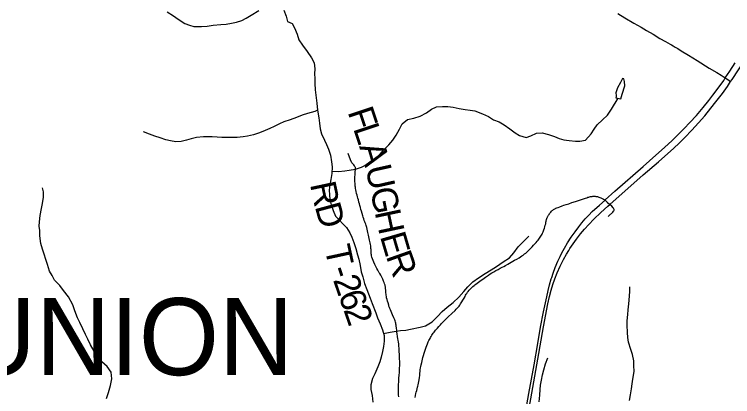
# Model space of a CAD drawing. Extents: x 0 to 34, y 0 to 22.
# Drawn here: x 5.781 to 7.37, y 19.464 to 20.31 of the extents above; entities that cross this region are included whole.
import ezdxf

# ---------------------------------------------------------------- set-up
doc = ezdxf.new("R2010")
doc.units = 0
for name, color, linetype in [('GM_X_County_Road', 7, 'Continuous'), ('GM_X_Minor_Lake', 7, 'Continuous'), ('GM_X_Minor_River', 7, 'Continuous'), ('GM_X_Township_Road', 7, 'Continuous'), ('GM_X_Township_Road_Text', 7, 'Continuous'), ('GM_X_Township_Text', 7, 'Continuous'), ('GM_X_US_Route', 7, 'Continuous')]:
    doc.layers.add(name, color=color, linetype=linetype)

msp = doc.modelspace()

# ---------------------------------------------------------------- linework, layer by layer
at = {"layer": 'GM_X_County_Road'}
for points in [[(6.9602, 19.8606), (6.9605, 19.8614), (6.9611, 19.8628), (6.9618, 19.8639), (6.9626, 19.8652), (6.9638, 19.8671), (6.9651, 19.8689), (6.9663, 19.8706), (6.9678, 19.8723), (6.9693, 19.8739), (6.9708, 19.8753), (6.9723, 19.8764), (6.9739, 19.8776), (6.9751, 19.8784), (6.9763, 19.8791), (6.9778, 19.88), (6.9791, 19.8806), (6.9809, 19.8814), (6.9837, 19.8824), (6.9874, 19.8838), (6.9927, 19.8857), (6.9968, 19.8872), (7.0018, 19.8888), (7.0076, 19.8907), (7.0145, 19.893), (7.0226, 19.8958), (7.0447, 19.9032), (7.0474, 19.904), (7.0499, 19.9048), (7.0518, 19.9054), (7.0535, 19.9058), (7.0553, 19.9063), (7.0572, 19.9067), (7.059, 19.9069), (7.0607, 19.9071), (7.0625, 19.9072), (7.0641, 19.9072), (7.0659, 19.9071), (7.0675, 19.9069), (7.0692, 19.9068), (7.071, 19.9064), (7.0724, 19.906), (7.0741, 19.9054), (7.0765, 19.9046), (7.0788, 19.9036), (7.0812, 19.9025), (7.0842, 19.9009), (7.0877, 19.8986)], [(7.0877, 19.8986), (7.0928, 19.894), (7.0982, 19.8889)], [(6.6674, 19.4617), (6.6683, 19.4666), (6.6694, 19.4706), (6.67, 19.474), (6.671, 19.4776), (6.672, 19.4811), (6.6731, 19.4849), (6.6738, 19.4873), (6.6744, 19.4902), (6.6751, 19.4934), (6.6757, 19.497), (6.6764, 19.5008), (6.6773, 19.5065), (6.6777, 19.5104), (6.678, 19.5134), (6.6782, 19.516), (6.6786, 19.5196), (6.679, 19.5234), (6.6797, 19.5272), (6.6803, 19.5307), (6.6811, 19.5342), (6.6821, 19.5393), (6.6829, 19.5428), (6.6837, 19.5464), (6.6848, 19.5507), (6.6859, 19.555), (6.6874, 19.5602), (6.6887, 19.5642), (6.6905, 19.5692), (6.6919, 19.5733), (6.6933, 19.5772), (6.6947, 19.5807), (6.6956, 19.583), (6.6967, 19.5853), (6.6979, 19.5877), (6.6991, 19.59), (6.7005, 19.5927), (6.7015, 19.5946), (6.703, 19.597), (6.7048, 19.5998), (6.7062, 19.6019), (6.7078, 19.6043), (6.7095, 19.6066), (6.7112, 19.6088), (6.7128, 19.6108), (6.7144, 19.6127), (6.7167, 19.6154), (6.7197, 19.6188), (6.7234, 19.623), (6.726, 19.6256), (6.7288, 19.6286), (6.7311, 19.631), (6.7339, 19.6338), (6.7371, 19.6369), (6.7408, 19.6405), (6.7487, 19.6479), (6.7558, 19.6546), (6.7587, 19.6575), (6.7606, 19.6597), (6.7626, 19.6619), (6.7648, 19.6643), (6.7662, 19.6664), (6.768, 19.6689), (6.7694, 19.6711), (6.771, 19.6738), (6.7729, 19.6771), (6.7758, 19.682), (6.778, 19.6857), (6.7793, 19.6881), (6.7806, 19.6902), (6.7819, 19.6922), (6.7837, 19.6946), (6.7852, 19.6967), (6.7871, 19.6991), (6.7886, 19.7008), (6.7902, 19.7026), (6.7916, 19.704), (6.7931, 19.7054), (6.7954, 19.7075), (6.7978, 19.7095), (6.7997, 19.711), (6.8018, 19.7126), (6.805, 19.7151), (6.8138, 19.7215), (6.8174, 19.724), (6.8234, 19.7283), (6.8297, 19.7326), (6.8338, 19.7353), (6.8373, 19.7375), (6.8417, 19.7401), (6.8463, 19.7428), (6.8512, 19.7454), (6.8559, 19.7479), (6.8599, 19.7501), (6.8635, 19.752), (6.8677, 19.7542), (6.8724, 19.7568), (6.8877, 19.7654), (6.8928, 19.7683), (6.8976, 19.7711), (6.9005, 19.7729), (6.9038, 19.7751), (6.9067, 19.777), (6.9099, 19.7794), (6.9124, 19.7815), (6.9148, 19.7836), (6.9174, 19.7861), (6.9201, 19.7889), (6.9236, 19.7926), (6.9264, 19.7955), (6.9296, 19.7987), (6.9324, 19.8019), (6.9351, 19.805), (6.9373, 19.8075), (6.9395, 19.8102), (6.9413, 19.8124), (6.943, 19.8146), (6.9444, 19.8167), (6.9458, 19.8187), (6.9472, 19.8213), (6.9483, 19.8233), (6.9495, 19.8257), (6.9506, 19.8281), (6.9516, 19.8305), (6.9526, 19.8332), (6.9537, 19.8362), (6.9546, 19.8396), (6.9556, 19.8433), (6.9564, 19.8464), (6.9571, 19.8496), (6.9578, 19.8524), (6.9585, 19.8555), (6.9593, 19.8582), (6.9599, 19.8599), (6.9602, 19.8606)]]:
    msp.add_lwpolyline(points, dxfattribs=at)
at = {"layer": 'GM_X_Minor_Lake'}
for points in [[(7.1228, 20.1227), (7.1259, 20.1329), (7.1315, 20.1514), (7.1305, 20.1613), (7.129, 20.1666), (7.1264, 20.1678), (7.1217, 20.1591), (7.1151, 20.1467), (7.1119, 20.1357), (7.1122, 20.13)], [(7.1122, 20.13), (7.1121, 20.1272), (7.1114, 20.1249), (7.1228, 20.1227)]]:
    msp.add_lwpolyline(points, dxfattribs=at)
at = {"layer": 'GM_X_Minor_River'}
for points in [[(6.119, 20.3149), (6.1329, 20.3064), (6.1431, 20.2986), (6.1581, 20.2897), (6.1683, 20.2858), (6.1781, 20.2826), (6.1948, 20.2824), (6.2073, 20.2837), (6.2206, 20.2855), (6.2377, 20.2871), (6.2495, 20.2881), (6.2616, 20.2898), (6.2723, 20.2923), (6.2841, 20.296), (6.294, 20.3011), (6.3051, 20.3078), (6.3219, 20.3182)], [(6.3772, 20.319), (6.3824, 20.3053), (6.3849, 20.2939), (6.3954, 20.2895), (6.4003, 20.28), (6.4065, 20.2659), (6.4101, 20.2529), (6.4183, 20.2411), (6.4284, 20.2277), (6.4385, 20.2135), (6.4444, 20.202), (6.4457, 20.1888), (6.4452, 20.1781), (6.4455, 20.1675), (6.4453, 20.1569), (6.4463, 20.1425), (6.4483, 20.1246), (6.4497, 20.1132), (6.4518, 20.0973), (6.4542, 20.0809), (6.4556, 20.0688), (6.4577, 20.0566), (6.4606, 20.0452), (6.4669, 20.0311), (6.4713, 20.0216), (6.4757, 20.0113), (6.4801, 19.9979), (6.4826, 19.9835), (6.4839, 19.9725), (6.483, 19.9573), (6.4809, 19.9441), (6.4789, 19.9327), (6.4776, 19.9206), (6.4779, 19.9104), (6.4785, 19.9001), (6.4814, 19.8879), (6.4865, 19.8754), (6.4917, 19.8628), (6.516, 19.8378), (6.5234, 19.8263), (6.5275, 19.8164), (6.5319, 19.8046), (6.5366, 19.7913), (6.5402, 19.7776), (6.5432, 19.7677), (6.546, 19.754), (6.5485, 19.7399), (6.5518, 19.7289), (6.5554, 19.714), (6.5605, 19.7011), (6.5642, 19.6911), (6.5679, 19.6816), (6.5723, 19.6698), (6.5803, 19.6492), (6.584, 19.6385), (6.5899, 19.6248), (6.5954, 19.6118), (6.5987, 19.5993), (6.5993, 19.5864), (6.5976, 19.5746), (6.5952, 19.5637), (6.5924, 19.5512), (6.5892, 19.5406), (6.5853, 19.5297), (6.5786, 19.5146), (6.5732, 19.5037), (6.5696, 19.4897), (6.5695, 19.4795), (6.5727, 19.4662), (6.5737, 19.4517)], [(6.4833, 19.9628), (6.4978, 19.9617), (6.5119, 19.9637), (6.5218, 19.9648), (6.5358, 19.9668), (6.5491, 19.9712), (6.564, 19.9793), (6.5759, 19.9871), (6.587, 19.9965), (6.5974, 20.0089), (6.6093, 20.0212), (6.6181, 20.0309), (6.6255, 20.0426), (6.6332, 20.0554), (6.6387, 20.0671), (6.6509, 20.0768), (6.665, 20.0796), (6.6787, 20.0843), (6.6928, 20.0914), (6.7039, 20.0995), (6.7146, 20.1051), (6.7279, 20.106), (6.7396, 20.1059), (6.7514, 20.1042), (6.765, 20.1014), (6.7782, 20.0993), (6.7892, 20.0976), (6.7994, 20.096), (6.8164, 20.0893), (6.8296, 20.0838), (6.8409, 20.0765), (6.8537, 20.0717), (6.8642, 20.0655), (6.8774, 20.0566), (6.889, 20.0477), (6.8988, 20.0415), (6.9132, 20.0372), (6.9235, 20.0408), (6.9364, 20.0467), (6.9489, 20.0473), (6.9629, 20.0437), (6.9758, 20.039), (6.9859, 20.035), (6.9965, 20.0322), (7.0086, 20.0302), (7.0223, 20.0289), (7.0321, 20.0291), (7.0443, 20.0316), (7.057, 20.0455), (7.0639, 20.0556), (7.0701, 20.0654), (7.082, 20.0762), (7.0931, 20.0867), (7.102, 20.0998), (7.1168, 20.1238)], [(6.4518, 20.0974), (6.4457, 20.0947), (6.4293, 20.09), (6.4175, 20.0864), (6.405, 20.0816), (6.3909, 20.0765), (6.3771, 20.0718), (6.3672, 20.0673), (6.3558, 20.0618), (6.3463, 20.057), (6.336, 20.0526), (6.3234, 20.0475), (6.3101, 20.0427), (6.2964, 20.0399), (6.2869, 20.0389), (6.274, 20.0375), (6.2645, 20.0373), (6.2535, 20.037), (6.2402, 20.0372), (6.2296, 20.0381), (6.2186, 20.0386), (6.2088, 20.0388), (6.1993, 20.0385), (6.1837, 20.0372), (6.1719, 20.0343), (6.1613, 20.0311), (6.1499, 20.0282), (6.1377, 20.0276), (6.1264, 20.0296), (6.1162, 20.0321), (6.1034, 20.0364), (6.0916, 20.0403), (6.0796, 20.0443), (6.0664, 20.0498)], [(5.985, 19.4597), (5.9893, 19.4729), (5.9933, 19.4884), (5.9962, 19.5031), (5.9948, 19.518), (5.9859, 19.5302), (5.9746, 19.5406), (5.9642, 19.5536), (5.9571, 19.5643), (5.9493, 19.5785), (5.943, 19.5911), (5.9379, 19.601), (5.9323, 19.614), (5.9253, 19.6277), (5.9205, 19.6384), (5.9146, 19.654), (5.9103, 19.667), (5.9006, 19.6849), (5.8894, 19.6987), (5.8812, 19.7099), (5.8696, 19.7218), (5.8641, 19.7317), (5.8585, 19.7413), (5.8538, 19.7561), (5.8505, 19.7675), (5.8465, 19.7793), (5.8432, 19.79), (5.8392, 19.8026), (5.8371, 19.8197), (5.8369, 19.8314), (5.8359, 19.8413), (5.8364, 19.8508), (5.8377, 19.8648), (5.8405, 19.8803), (5.8433, 19.8912), (5.8454, 19.9052), (5.8455, 19.9166), (5.8434, 19.9261)], [(6.5975, 19.6036), (6.612, 19.6063), (6.6253, 19.6084), (6.6352, 19.6098), (6.647, 19.6111), (6.6576, 19.6129), (6.6789, 19.6172), (6.6903, 19.6208), (6.7052, 19.6293), (6.7171, 19.6413), (6.7271, 19.6525), (6.7386, 19.6615), (6.752, 19.6723), (6.7646, 19.6839), (6.775, 19.6966), (6.7839, 19.7067), (6.795, 19.718), (6.808, 19.7265), (6.8226, 19.7365), (6.8355, 19.7447), (6.8478, 19.7521), (6.8627, 19.7618), (6.8761, 19.7707), (6.8861, 19.7819), (6.8957, 19.7955), (6.908, 19.8078), (6.9188, 19.819)], [(7.142, 19.455), (7.1444, 19.4675), (7.1465, 19.4811), (7.1474, 19.4924), (7.1494, 19.5023), (7.1519, 19.5197), (7.1517, 19.5326), (7.1511, 19.5428), (7.1482, 19.5573), (7.1446, 19.5683), (7.1399, 19.5843), (7.1381, 19.5946), (7.1371, 19.6056), (7.1365, 19.6223), (7.137, 19.6318), (7.138, 19.6454), (7.1392, 19.6556), (7.1405, 19.6693), (7.1419, 19.6859), (7.1424, 19.6969), (7.1429, 19.7064)], [(6.9422, 19.4524), (6.9435, 19.4668), (6.9444, 19.4793), (6.9453, 19.4891), (6.947, 19.5005), (6.9494, 19.5122), (6.9522, 19.5232), (6.9558, 19.5364), (6.9609, 19.55)]]:
    msp.add_lwpolyline(points, dxfattribs=at)
at = {"layer": 'GM_X_Township_Road'}
for points in [[(7.1163, 20.3115), (7.1318, 20.3021), (7.1518, 20.2903), (7.168, 20.2809), (7.1794, 20.2742), (7.1939, 20.2656), (7.2093, 20.2564), (7.2218, 20.2492), (7.2269, 20.2462), (7.2315, 20.2438), (7.2345, 20.2421), (7.2382, 20.2399), (7.2431, 20.2371), (7.2487, 20.2338), (7.2565, 20.2289), (7.2723, 20.219), (7.2913, 20.2073), (7.3185, 20.1907), (7.3348, 20.1807), (7.3446, 20.1747), (7.3539, 20.1688)], [(7.3539, 20.1688), (7.3594, 20.1651), (7.3657, 20.1608)], [(6.6312, 19.4632), (6.6311, 19.468), (6.631, 19.4746), (6.631, 19.4804), (6.631, 19.4859), (6.6311, 19.491), (6.6313, 19.4966), (6.6314, 19.5005), (6.6316, 19.5045), (6.6321, 19.5115), (6.6326, 19.517), (6.6331, 19.5264), (6.6335, 19.5333), (6.6335, 19.5378), (6.6334, 19.5423), (6.6333, 19.5467), (6.6332, 19.5508), (6.633, 19.5565), (6.6325, 19.5643), (6.6322, 19.5705), (6.6317, 19.576), (6.6313, 19.5804), (6.6307, 19.5844), (6.6302, 19.5885), (6.6296, 19.5918), (6.6287, 19.597), (6.6278, 19.6029), (6.6273, 19.6064), (6.6268, 19.6098), (6.6261, 19.616), (6.6257, 19.62), (6.6255, 19.6222), (6.6252, 19.6243), (6.6248, 19.6264), (6.6243, 19.6288), (6.6233, 19.6315), (6.6224, 19.634), (6.6205, 19.6385), (6.6178, 19.6446), (6.6143, 19.6523), (6.6128, 19.6556), (6.6115, 19.6589), (6.6106, 19.6612), (6.6097, 19.6638), (6.609, 19.6663), (6.6076, 19.671), (6.6065, 19.675), (6.6054, 19.679), (6.6045, 19.6827), (6.6039, 19.6856), (6.6034, 19.6884), (6.6031, 19.6909), (6.6029, 19.6933), (6.6027, 19.6962), (6.6025, 19.6995), (6.6022, 19.7031), (6.6018, 19.7064), (6.6015, 19.7083), (6.6009, 19.7108), (6.6001, 19.7134), (6.5991, 19.7161), (6.5978, 19.7195), (6.5963, 19.7234), (6.5949, 19.7266), (6.5934, 19.7295), (6.5917, 19.7327), (6.5897, 19.7359), (6.5883, 19.738), (6.5868, 19.7406), (6.5851, 19.7433), (6.5831, 19.747), (6.5815, 19.75), (6.5799, 19.7531), (6.5785, 19.7562), (6.5764, 19.761), (6.5746, 19.7651), (6.5731, 19.769), (6.5719, 19.7726), (6.5712, 19.7751), (6.5707, 19.7774), (6.5702, 19.7799), (6.57, 19.7836), (6.5699, 19.7867), (6.5699, 19.789), (6.5698, 19.7917), (6.5697, 19.7946), (6.5694, 19.7973), (6.569, 19.8002), (6.5681, 19.8044), (6.5676, 19.8068), (6.5668, 19.8098), (6.566, 19.8135), (6.5651, 19.8174), (6.5641, 19.8212), (6.5634, 19.8242), (6.5628, 19.8269), (6.562, 19.8307), (6.5612, 19.8344), (6.5605, 19.8378), (6.5599, 19.8399), (6.5591, 19.8424), (6.5581, 19.8456), (6.557, 19.8486), (6.5561, 19.8509), (6.5551, 19.8537), (6.554, 19.8569), (6.5527, 19.8606), (6.5515, 19.8641), (6.5501, 19.8688), (6.5486, 19.8741), (6.5475, 19.8782), (6.5464, 19.8823), (6.5453, 19.8869), (6.5443, 19.8906), (6.5433, 19.8941), (6.542, 19.899), (6.5408, 19.9031), (6.5399, 19.9061), (6.539, 19.9093), (6.538, 19.9134), (6.537, 19.9176), (6.5364, 19.921), (6.5358, 19.9243), (6.5353, 19.9272), (6.5349, 19.9297), (6.5346, 19.9333), (6.5345, 19.9363), (6.5344, 19.9389), (6.5342, 19.9429), (6.5342, 19.9468), (6.5343, 19.9502), (6.5345, 19.9548), (6.5347, 19.9585), (6.535, 19.9622), (6.5354, 19.9657), (6.5356, 19.9677), (6.5355, 19.9692), (6.5353, 19.9708), (6.5351, 19.9718), (6.5335, 19.9746), (6.5317, 19.9766), (6.5299, 19.9786), (6.5277, 19.9812), (6.5246, 19.9876), (6.5196, 20.0018)], [(7.0946, 19.8623), (7.0962, 19.864), (7.1047, 19.872), (7.1066, 19.8739), (7.1074, 19.875), (7.1079, 19.8764), (7.1079, 19.8779), (7.1075, 19.8793), (7.1068, 19.8806), (7.1058, 19.8816), (7.1025, 19.8849), (7.0982, 19.8889)]]:
    msp.add_lwpolyline(points, dxfattribs=at)
at = {"layer": 'GM_X_US_Route'}
for points in [[(7.3657, 20.1608), (7.3691, 20.1657), (7.3831, 20.187), (7.3923, 20.2017), (7.4005, 20.2156), (7.4099, 20.2324), (7.422, 20.2555), (7.4277, 20.2665)], [(6.9697, 19.7274), (6.9729, 19.7369), (6.9777, 19.7496), (6.9834, 19.7634), (6.9883, 19.7741), (6.9924, 19.7823), (6.9978, 19.7921), (7.0048, 19.8038), (7.0128, 19.8163), (7.0213, 19.8286), (7.0294, 19.8395), (7.0364, 19.8482), (7.044, 19.8571), (7.0517, 19.8652), (7.0596, 19.8731), (7.0756, 19.8878), (7.0877, 19.8986), (7.0883, 19.8992), (7.1093, 19.9181), (7.1724, 19.9733), (7.2004, 19.9979), (7.2194, 20.0149), (7.2362, 20.0306), (7.2536, 20.0475), (7.2628, 20.0568), (7.2756, 20.0704), (7.2898, 20.0861), (7.3048, 20.1035), (7.3174, 20.1189), (7.3266, 20.1307), (7.3381, 20.1462), (7.3503, 20.1634), (7.3539, 20.1688), (7.3638, 20.1836), (7.3759, 20.2024)], [(7.0982, 19.8889), (7.1724, 19.9542), (7.2057, 19.9832), (7.24, 20.0138), (7.2517, 20.0248), (7.2641, 20.0371), (7.2799, 20.0536), (7.2947, 20.0696), (7.3082, 20.085), (7.3221, 20.1017), (7.3332, 20.1159), (7.3474, 20.1347), (7.3586, 20.1503), (7.3657, 20.1608)], [(7.0075, 19.7871), (7.0101, 19.7915), (7.017, 19.8018), (7.0246, 19.8125), (7.0334, 19.8238), (7.0421, 19.8343), (7.0518, 19.8449), (7.0632, 19.8564), (7.0785, 19.871), (7.0941, 19.8853), (7.0982, 19.8889)], [(6.8834, 19.2378), (6.8838, 19.2398), (6.8967, 19.3106), (6.9145, 19.4102), (6.9234, 19.459), (6.9391, 19.547), (6.9519, 19.6185), (6.9613, 19.6691), (6.9648, 19.6855), (6.9683, 19.6994), (6.9721, 19.7119), (6.9764, 19.7243), (6.9818, 19.7375), (6.9885, 19.7522), (6.996, 19.7673), (7.0027, 19.7793), (7.0075, 19.7871)], [(6.9095, 19.4165), (6.9191, 19.4709), (6.9307, 19.5343), (6.9389, 19.5814), (6.9453, 19.6175), (6.9518, 19.6516), (6.9586, 19.685), (6.9617, 19.6989), (6.9649, 19.7115), (6.9687, 19.7246), (6.9697, 19.7274)]]:
    msp.add_lwpolyline(points, dxfattribs=at)

# ---------------------------------------------------------------- texts
at = {"layer": 'GM_X_Township_Road_Text'}
for s, rotation, p in [('F', 288.4335, (6.5179, 20.0939)), ('L', 288.3814, (6.53, 20.0575)), ('A', 286.3247, (6.5433, 20.0177)), ('U', 282.596, (6.5571, 19.9707)), ('R', 281.9755, (6.4347, 19.9338)), ('G', 281.1331, (6.5679, 19.9223)), ('D', 285.2545, (6.4452, 19.8848)), ('H', 281.9975, (6.5778, 19.8723)), ('E', 286.3289, (6.5893, 19.8188)), ('T', 282.2076, (6.4669, 19.7932)), ('R', 289.5084, (6.6023, 19.7748)), ('-', 288.7783, (6.4777, 19.7448)), ('2', 289.1791, (6.4854, 19.7223)), ('6', 289.2326, (6.4969, 19.6892)), ('2', 289.2541, (6.5084, 19.6561))]:
    msp.add_text(s, height=0.0568, rotation=rotation, dxfattribs=at).set_placement(p)
at = {"layer": 'GM_X_Township_Text'}
msp.add_text('UNION', height=0.17045, rotation=0, dxfattribs=at).set_placement((5.6638, 19.5114))

doc.saveas('drawing.dxf')
